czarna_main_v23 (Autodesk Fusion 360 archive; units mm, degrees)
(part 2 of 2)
sketch "Sketch1" plane through (0, 0, -98.4) normal (0, 0, 1) x axis (-1, 0, 0)
  line L1 (-270, 360.5) -> (270, 360.5)
  line L2 (-270, 342.5) -> (-270, 360.5)
  line L3 (270, 342.5) -> (-270, 342.5)
  line L4 (270, 360.5) -> (270, 342.5)
  line L5 (-249, -175.5) -> (-249, 360.5)
  line L6 (-270, 360.5) -> (-249, 360.5)
  line L7 (-270, 342.5) -> (-270, 360.5)
  line L8 (-249, 342.5) -> (-270, 342.5)
  line L9 (-249, 360.5) -> (-249, 342.5)
  line L10 (-272, 362.5) -> (-247, 362.5)
  line L11 (-272, 340.5) -> (-272, 362.5)
  line L12 (-247, 340.5) -> (-272, 340.5)
  line L13 (-247, 362.5) -> (-247, 340.5)
  line L14 (-249, 362.5) -> (-249, 360.5)
  point P4 (-270, 342.5)
  point P10 (-270, 342.5)
  point P6 (-249, 360.5)
  point P8 (-249, 360.5)
  point P16 (-249, 360.5)
  point P17 (-249, 362.5)
  horizontal L6
  vertical L7
  horizontal L8
  vertical L9
  coincident P4 P10
  coincident P6 P8
  coincident P6 P16
  coincident L10 P17
  perpendicular L10 L14
  dimension "d1" = 2
extrude "Extrude1" new body sketch "Sketch1" profile of L1 L2 L3 L5 L6 L7 L8 L9 L10 L12 L11 L14 along normal blind 18
extrude "Extrude2" add sketch "Sketch1" profile of L1 L2 L3 L5 L6 L7 L8 L10 L12 L11 L14 against normal blind 3
fillet "Fillet1" radius 5
fillet "Fillet2" radius 1
sketch "Sketch2" plane through (0, 0, -80.4) normal (0, 0, 1) x axis (-1, 0, 0)
  line L1 (-249, 341.5) -> (-267, 341.5)
  line L2 (-249, 361.5) -> (-249, 341.5)
  line L3 (-267, 361.5) -> (-249, 361.5)
  line L4 (-267, 341.5) -> (-267, 361.5)
  line L5 (-267, 351.5) -> (-249, 351.5)
  line L6 (-258, 361.5) -> (-258, 341.5)
  circle C1 centre (-258, 351.5) radius 2.5
  point P6 (-249, 351.5)
  point P7 (-267, 351.5)
  point P8 (-258, 341.5)
  point P9 (-258, 361.5)
  point P10 (-258, 351.5)
  midpoint L2 P6
  midpoint L4 P7
  midpoint L1 P8
  midpoint L3 P9
  midpoint L6 P10
  dimension "d10" diameter C1 = 5
extrude "Extrude3" cut sketch "Sketch2" profile of C1 against normal blind 18
chamfer "Chamfer1" distance 3
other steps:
derived_base_feature "Derived Base Feature1" bodies "Body1"
derived_base_feature "Derived Base Feature2" bodies "Body1 (1)"
named bodies: "Body1", "Body1 (1)"

design "front_zetki"
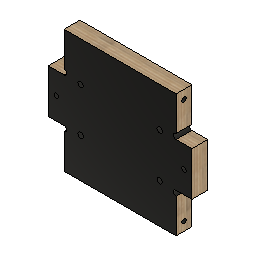
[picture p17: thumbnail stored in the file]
derived_context "$ 6e871250-6ba1-47b6-a885-2dd81215d881㸩忾盧繧$ a4974d71-8db2-4fde-91a5-83f0541c0199́   Ā䢀켓훟␀ 䔀㌰㠷䔴ⵄ䔵㤱㐭ㅅⴴ㥂㉆㌭あ〷㜱㄰䌸D  czarnula_main v53     Ā¶          뼁    Ā Āǹ   ᜁ齭冀梗æ$ ㍄㌹〷㠲䌭〲ⵃ"
sketch "Sketch1" plane through (-78.7594, 79.012, 28.9318) normal (1, 0, 0) x axis (0, 1, 0)
  line L1 (-158.024, -57.8636) -> (-258.024, -57.8636)
  line L2 (-158.024, 82.1364) -> (-158.024, -57.8636)
  line L3 (-258.024, 82.1364) -> (-158.024, 82.1364)
  line L4 (-258.024, -57.8636) -> (-258.024, 82.1364)
  line L5 (-240.024, 82.1364) -> (-258.024, 82.1364)
  line L6 (-240.024, -57.8636) -> (-240.024, 82.1364)
  line L7 (-258.024, -57.8636) -> (-240.024, -57.8636)
  line L8 (-258.024, 82.1364) -> (-258.024, -57.8636)
  circle C1 centre (-168.024, 42.1364) radius 2.5
  circle C2 centre (-200.024, -17.8636) radius 2.5
  circle C3 centre (-200.024, 42.1364) radius 2.5
  circle C4 centre (-168.024, -17.8636) radius 2.5
  circle C5 centre (-249.024, 72.1364) radius 2.5
  circle C6 centre (-249.024, -47.8636) radius 2.5
  circle C7 centre (-249.024, 12.1364) radius 2.5
  point P12 (-258.024, 82.1364)
  point P13 (-258.024, 82.1364)
  point P14 (-240.024, 82.1364)
  point P16 (-258.024, -57.8636)
  horizontal L5
  vertical L6
  horizontal L7
  vertical L8
  coincident P12 P13
  dimension "d1" distance P13 P14 = 18
  dimension "d2" distance P13 P16 = 140
extrude "Extrude1" new body sketch "Sketch1" profile of C5 C6 C7 L1 L3 L4 L5 L6 L7 L8 along normal blind 127.5
sketch "Sketch2" plane through (0, -179.012, 0) normal (0, -1, 0) x axis (1, 0, 0)
  line L1 (-78.7594, -28.9318) -> (-78.7594, 111.0682)
  line L2 (48.7406, -28.9318) -> (-78.7594, -28.9318)
  line L3 (48.7406, 111.0682) -> (48.7406, -28.9318)
  line L4 (-78.7594, 111.0682) -> (48.7406, 111.0682)
  line L5 (-15.0094, -28.9318) -> (-15.0094, 111.0682)
  line L6 (48.7406, 41.0682) -> (-78.7594, 41.0682)
  circle C1 centre (-60.0094, 66.0682) radius 3
  circle C2 centre (29.9906, 66.0682) radius 3
  circle C3 centre (-60.0094, 16.0682) radius 3
  circle C4 centre (29.9906, 16.0682) radius 3
  point P6 (-15.0094, 111.0682)
  point P7 (-15.0094, -28.9318)
  point P8 (-78.7594, 41.0682)
  point P9 (48.7406, 41.0682)
  point P10 (-60.0094, 66.0682)
  midpoint L4 P6
  midpoint L2 P7
  midpoint L1 P8
  midpoint L3 P9
  symmetric L5 C1 C2
  symmetric L6 C1 C3
  symmetric L6 C2 C4
  dimension "d5" diameter C1 = 6
  dimension "d6" distance L5 P10 = 45
  dimension "d7" distance L6 P10 = 25
extrude "Extrude2" cut sketch "Sketch2" profile of C1 C2 C3 C4 against normal blind 25
sketch "Szkic3" plane through (48.7406, 0, 0) normal (1, 0, 0) x axis (0, 1, 0)
  line L1 (-161.012, -28.9318) -> (-179.012, -28.9318)
  line L2 (-161.012, 111.0682) -> (-161.012, -28.9318)
  line L3 (-179.012, 111.0682) -> (-161.012, 111.0682)
  line L4 (-179.012, -28.9318) -> (-179.012, 111.0682)
  line L5 (-161.012, 16.0682) -> (-179.012, 16.0682)
  line L6 (-161.012, 66.0682) -> (-161.012, 16.0682)
  line L7 (-179.012, 66.0682) -> (-161.012, 66.0682)
  line L8 (-179.012, 16.0682) -> (-179.012, 66.0682)
  line L9 (-161.012, 66.0682) -> (-179.012, 16.0682)
  line L10 (-179.012, 66.0682) -> (-161.012, 16.0682)
  circle C1 centre (-170.012, 101.0682) radius 2.5
  circle C2 centre (-170.012, 41.0682) radius 2.5
  circle C3 centre (-170.012, -18.9318) radius 2.5
  point P13 (-170.012, 41.0682)
  point P3 (-170.012, 41.0682)
  point P11 (-161.012, 66.0682)
  point P12 (-179.012, 66.0682)
  point P10 (-161.012, 16.0682)
  horizontal L5
  perpendicular L5 L6
  parallel L5 L7
  parallel L6 L8
  coincident L9 P13
  coincident L10 P13
  coincident P3 P13
  dimension "d10" distance P11 P12 = 18
  dimension "d11" distance P10 P11 = 50
extrude "Wyciągnięcie proste3" add sketch "Szkic3" profile of C2 L2 L4 L5 L6 L7 L8 along normal blind 18
work_plane "Płaszczyzna konstrukcyjna"
mirror "Odbij1" mirrorStitchTolerance 0.1
sketch "Szkic4" plane through (0, -179.012, 0) normal (0, -1, 0) x axis (1, 0, 0)
  line L1 (-78.7594, -28.9318) -> (-78.7594, 16.0682)
  line L2 (48.7406, -28.9318) -> (-78.7594, -28.9318)
  line L3 (48.7406, 16.0682) -> (48.7406, -28.9318)
  line L4 (66.7406, 16.0682) -> (48.7406, 16.0682)
  line L5 (66.7406, 66.0682) -> (66.7406, 16.0682)
  line L6 (48.7406, 66.0682) -> (66.7406, 66.0682)
  line L7 (48.7406, 111.0682) -> (48.7406, 66.0682)
  line L8 (-78.7594, 111.0682) -> (48.7406, 111.0682)
  line L9 (-78.7594, 66.0682) -> (-78.7594, 111.0682)
  line L10 (-96.7594, 66.0682) -> (-78.7594, 66.0682)
  line L11 (-96.7594, 16.0682) -> (-96.7594, 66.0682)
  line L12 (-78.7594, 16.0682) -> (-96.7594, 16.0682)
  circle C1 centre (29.9906, 66.0682) radius 3
  circle C2 centre (29.9906, 16.0682) radius 3
  circle C3 centre (-60.0094, 66.0682) radius 3
  circle C4 centre (-60.0094, 16.0682) radius 3
  circle C5 centre (48.7406, 69.0682) radius 3
  circle C6 centre (48.7406, 13.0682) radius 3
  circle C7 centre (57.7406, 41.0682) radius 2.5
  point P18 (48.7406, 69.0682)
  point P19 (48.7406, 13.0682)
  point P20 (57.7406, 41.0682)
  coincident L7 P18
  coincident L3 P19
  dimension "d16" diameter C5 = 6
  dimension "d17" diameter C6 = 6
  dimension "d18" distance L4 P19 = 3
  dimension "d19" distance L6 P18 = 3
  dimension "d24" diameter C7 = 5
  dimension "d25" distance L4 P20 = 25
  dimension "d26" distance L5 P20 = 9
extrude "Wyciągnięcie proste4" cut sketch "Szkic4" profile of L3 L7 C5 C6 C7 against normal blind 20
mirror "Odbij2" mirrorStitchTolerance 0.1
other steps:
derived_base_feature "Derived Base Feature" bodies "Body1"
named bodies: "Body1"

design "karetka_dol"
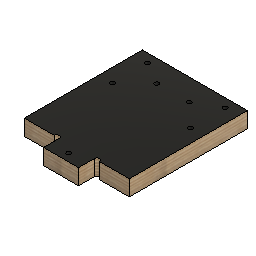
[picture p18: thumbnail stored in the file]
derived_context "$ 849fbd61-1d81-4a9c-a9ca-583caa0cf6c6챱窴Ც똯$ a4974d71-8db2-4fde-91a5-83f0541c0199́   Ā压롻䈮␀ 䔀㌰㠷䔴ⵄ䔵㤱㐭ㅅⴴ㥂㉆㌭あ〷㜱㄰䌸D  czarnula_main v45     Ā¶          뼁    Ā ĀŦ   먁䡹䫷>$ ㍄㌹〷㠲䌭〲ⵃ"
derived_context "Kontekst pochodny"
sketch "Sketch1" plane through (14, -5, -1) normal (0, -1, 0) x axis (1, 0, 0)
  line L1 (13.6, 5.7) -> (13.6, 4.3)
  line L2 (31, -23) -> (-89, -23)
  line L3 (31, 157) -> (31, -23)
  line L4 (-89, 157) -> (31, 157)
  line L5 (-89, -23) -> (-89, 157)
  line L6 (31, -23) -> (-89, -23)
  line L7 (31, -5) -> (31, -23)
  line L8 (-89, -5) -> (31, -5)
  line L9 (-89, -23) -> (-89, -5)
  arc A1 centre (16, 5) radius 2.5 clockwise from (13.6, 5.7) to (13.6, 4.3)
  circle C1 centre (16, 95) radius 2.5
  circle C2 centre (16, 127) radius 2.5
  circle C3 centre (16, 37) radius 2.5
  circle C4 centre (-74, 81) radius 2.5
  circle C5 centre (-44, 5) radius 2.5
  circle C6 centre (-44, 95) radius 2.5
  circle C7 centre (-44, 127) radius 2.5
  circle C8 centre (-44, 37) radius 2.5
  circle C9 centre (-74, 51) radius 2.5
  point P14 (-89, -23)
  point P18 (-89, -23)
  point P19 (31, -23)
  point P21 (-89, -5)
  horizontal L6
  vertical L7
  horizontal L8
  vertical L9
  coincident P14 P18
  dimension "d1" distance P18 P19 = 120
  dimension "d2" distance P18 P21 = 18
extrude "Extrude1" new body sketch "Sketch1" profile of L2 L3 L5 L6 L7 L8 L9 along normal blind 130
sketch "Sketch2" plane through (0, -135, 0) normal (0, -1, 0) x axis (1, 0, 0)
  line L1 (-75, -24) -> (-75, -6)
  line L2 (45, -24) -> (-75, -24)
  line L3 (45, -6) -> (45, -24)
  line L4 (-75, -6) -> (45, -6)
  line L5 (45, -15) -> (-75, -15)
  line L6 (-15, -24) -> (-15, -6)
  line L7 (5, -6) -> (-35, -6)
  line L8 (5, -24) -> (5, -6)
  line L9 (-35, -24) -> (5, -24)
  line L10 (-35, -6) -> (-35, -24)
  line L11 (5, -24) -> (-35, -6)
  line L12 (-35, -24) -> (5, -6)
  point P6 (-75, -15)
  point P7 (45, -15)
  point P8 (-15, -6)
  point P9 (-15, -24)
  point P14 (-15, -15)
  point P12 (5, -24)
  point P13 (-35, -24)
  point P11 (5, -6)
  midpoint L1 P6
  midpoint L3 P7
  midpoint L4 P8
  midpoint L2 P9
  horizontal L7
  perpendicular L7 L8
  parallel L7 L9
  parallel L8 L10
  coincident L11 P14
  coincident L12 P14
  midpoint L6 P14
  dimension "d5" distance P12 P13 = 40
  dimension "d6" distance P11 P12 = 18
extrude "Extrude2" add sketch "Sketch2" profile of L2 L4 L7 L8 L9 L10 along normal blind 18
sketch "Sketch3" plane through (0, 0, -6) normal (0, 0, 1) x axis (-1, 0, 0)
  line L1 (75, 5) -> (-45, 5)
  line L2 (75, 135) -> (75, 5)
  line L3 (35, 135) -> (75, 135)
  line L4 (35, 153) -> (35, 135)
  line L5 (-5, 153) -> (35, 153)
  line L6 (-5, 135) -> (-5, 153)
  line L7 (-45, 135) -> (-5, 135)
  line L8 (-45, 5) -> (-45, 135)
  circle C1 centre (38, 135) radius 3
  circle C2 centre (-8, 135) radius 3
  circle C3 centre (15, 144) radius 2.5
  point P10 (38, 135)
  point P11 (-8, 135)
  point P12 (15, 144)
  coincident L3 P10
  coincident L7 P11
  dimension "d9" diameter C1 = 6
  dimension "d10" diameter C2 = 6
  dimension "d11" distance L4 P10 = 3
  dimension "d12" distance L6 P11 = 3
  dimension "d13" diameter C3 = 5
  dimension "d14" distance L6 P12 = 20
  dimension "d15" distance L5 P12 = 9
extrude "Extrude3" cut sketch "Sketch3" profile of L3 L7 C1 C2 C3 against normal blind 21
sketch "Sketch4" plane through (0, 0, -6) normal (0, 0, 1) x axis (-1, 0, 0)
  line L1 (-45, 135) -> (-11, 135)
  line L2 (-45, 5) -> (-45, 135)
  line L3 (75, 5) -> (-45, 5)
  line L4 (75, 135) -> (75, 5)
  line L5 (41, 135) -> (75, 135)
  line L6 (35, 153) -> (35, 135)
  line L7 (-5, 153) -> (35, 153)
  line L8 (-5, 135) -> (-5, 153)
  line L9 (15, 153) -> (15, 5)
  circle C1 centre (15, 144) radius 2.5
  arc A1 centre (-8, 135) radius 3 clockwise from (-5, 135) to (-11, 135)
  arc A2 centre (38, 135) radius 3 clockwise from (41, 135) to (35, 135)
  circle C2 centre (59.5, 10) radius 2.5
  circle C3 centre (59.5, 50) radius 2.5
  circle C4 centre (-29.5, 10) radius 2.5
  circle C5 centre (-29.5, 50) radius 2.5
  point P15 (15, 5)
  point P16 (15, 153)
  point P17 (59.5, 10)
  point P18 (59.5, 50)
  midpoint L3 P15
  midpoint L7 P16
  vertical P17 P18
  symmetric L9 C2 C4
  symmetric L9 C3 C5
  dimension "d18" diameter C2 = 5
  dimension "d19" diameter C3 = 5
  dimension "d20" distance L4 P17 = 15.5
  dimension "d21" distance P17 P18 = 40
  dimension "d22" distance L7 P18 = 103
extrude "Extrude4" cut sketch "Sketch4" profile of C2 C3 C4 C5 against normal blind 20
extrude "Extrude5" add of existing geometry blind 5
sketch "Szkic" plane through (0, 0, -6) normal (0, 0, 1) x axis (-1, 0, 0)
  line L1 (-45, 135) -> (-11, 135)
  line L2 (-45, 0) -> (-45, 135)
  line L3 (75, 0) -> (-45, 0)
  line L4 (75, 135) -> (75, 0)
  line L5 (41, 135) -> (75, 135)
  line L6 (35, 153) -> (35, 135)
  line L7 (-5, 153) -> (35, 153)
  line L8 (-5, 135) -> (-5, 153)
  line L9 (4.4324, 11.6836) -> (-6.9189, 20.6918)
  line L10 (36.9189, 20.6918) -> (25.5676, 11.6836)
  line L11 (25.5676, 38.3164) -> (36.9189, 29.3083)
  line L12 (-6.9189, 29.3083) -> (4.4324, 38.3164)
  circle C1 centre (-29.5, 10) radius 2.5
  circle C2 centre (-29.5, 50) radius 2.5
  circle C3 centre (59.5, 10) radius 2.5
  circle C4 centre (59.5, 50) radius 2.5
  circle C5 centre (15, 144) radius 2.5
  arc A1 centre (-8, 135) radius 3 clockwise from (-5, 135) to (-11, 135)
  arc A2 centre (38, 135) radius 3 clockwise from (41, 135) to (35, 135)
  arc A3 centre (15, 25) radius 17 clockwise from (25.5676, 11.6836) to (4.4324, 11.6836)
  arc A4 centre (33.5, 25) radius 5.5 clockwise from (36.9189, 29.3083) to (36.9189, 20.6918)
  arc A5 centre (15, 25) radius 17 clockwise from (4.4324, 38.3164) to (25.5676, 38.3164)
  arc A6 centre (-3.5, 25) radius 5.5 clockwise from (-6.9189, 20.6918) to (-6.9189, 29.3083)
  arc A7 centre (33.5, 25) radius 4 clockwise from (30.9114, 21.9505) to (30.9114, 28.0495)
  arc A8 centre (15, 25) radius 16.201 clockwise from (30.9114, 21.9505) to (-0.9114, 21.9505)
  arc A9 centre (-3.5, 25) radius 4 clockwise from (-0.9114, 28.0495) to (-0.9114, 21.9505)
  arc A10 centre (15, 25) radius 16.201 clockwise from (-0.9114, 28.0495) to (30.9114, 28.0495)
  circle C6 centre (33.5, 25) radius 2.4
  circle C7 centre (-3.5, 25) radius 2.4
extrude "Wyciągnięcie proste" cut sketch "Szkic" profile of L7 C6 C7 against normal blind 18
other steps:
derived_base_feature "Derived Base Feature" bodies "Body1"
derived_base_feature "Pochodny element bazowy"
named bodies: "Body1"

design "Nakretka_TR8x8"
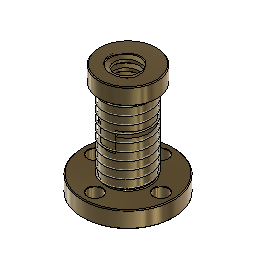
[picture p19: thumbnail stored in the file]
canvas "Canvas1"
sketch "Sketch1" plane through (0, 0, 0) normal (0, 0, 1) x axis (1, 0, 0)
  circle C1 centre (0, 0) radius 11
  circle C2 centre (0, 0) radius 3.25
  circle C3 centre (0, 0) radius 5.15
  circle C4 centre (0, 8) radius 1.75
  circle C5 centre (-8, 0) radius 1.75
  circle C6 centre (0, -8) radius 1.75
  circle C7 centre (8, 0) radius 1.75
  point P1 (0, 0)
  point P2 (0, 0)
  point P3 (0, 0)
  point P4 (0, 0)
  point P5 (0, 8)
  coincident P1 P2
  coincident P1 P3
  concentric C1 C3
  vertical P4 P5
  dimension "d1_1" diameter C1 = 22
  dimension "d2_1" diameter C2 = 6.5
  dimension "d3_1" diameter C3 = 10.3
  dimension "d4_2" diameter C4 = 3.5
  dimension "d5_2" distance P4 P5 = 8
  dimension "d7_2" C-Pattern1-Angle = 360
extrude "Extrude1" new body sketch "Sketch1" profile of C2 C3 along normal blind 15 named "d8_1"
extrude "Extrude2" add sketch "Sketch1" profile of C1 C3 C4 C5 C6 C7 along normal blind 4 named "d10_2"
sketch "Sketch2" plane through (0, 0, 15) normal (0, 0, 1) x axis (-1, 0, 0)
  line L1 (1.8, 8.9456) -> (-1.8, 8.9456)
  line L2 (1.8, -8.9456) -> (1.8, 8.9456)
  line L3 (-1.8, -8.9456) -> (1.8, -8.9456)
  line L4 (-1.8, 8.9456) -> (-1.8, -8.9456)
  line L5 (1.8, -8.9456) -> (-1.8, 8.9456)
  line L6 (-1.8, -8.9456) -> (1.8, 8.9456)
  circle C1 centre (0, 0) radius 3.25
  circle C2 centre (0, 0) radius 5.15
  point P7 (0, 0)
  point P1 (0, 0)
  point P5 (1.8, -8.9456)
  point P6 (-1.8, -8.9456)
  horizontal L1
  perpendicular L1 L2
  parallel L1 L3
  parallel L2 L4
  coincident L5 P7
  coincident L6 P7
  coincident P1 P7
  dimension "d12_2" distance P5 P6 = 3.6
extrude "Extrude3" add sketch "Sketch2" profile of C1 C2 L2 L4 against normal blind 3.6 named "d13_2"
extrude "Extrude4" cut sketch "Sketch2" profile of C1 C2 L2 L4 against normal blind 3.6 named "d15_1"
component_from_bodies "Body->Comp1"
thread "Thread1"
sketch "Sketch3" plane through (0, 0, 15) normal (0, 0, 1) x axis (-1, 0, 0)
  line L1 (-1.8, -2.5162) -> (-1.8, -4.8252)
  line L2 (-1.8, 4.8252) -> (-1.8, 2.5162)
  arc A1 centre (0, 0) radius 3.0937 clockwise from (-1.8, -2.5162) to (-1.8, 2.5162)
  arc A2 centre (0, 0) radius 5.15 clockwise from (-1.8, -4.8252) to (-1.8, 4.8252)
work_plane "WorkPlane1" sketch "Sketch3" AlongDistance 15 named "d17_2"
sketch "Sketch4" plane through (3.475, 0, 30) normal (0, 0, 1) x axis (1, 0, 0)
  line L1 (-1.725, -16) -> (-5.225, -16)
  line L2 (-1.725, 16) -> (-1.725, -16)
  line L3 (-5.225, 16) -> (-1.725, 16)
  line L4 (-5.225, -16) -> (-5.225, 16)
  line L5 (-1.725, 16) -> (-5.225, -16)
  line L6 (-5.225, 16) -> (-1.725, -16)
  circle C1 centre (-3.475, 0) radius 7
  circle C2 centre (-3.475, 0) radius 5.15
  circle C3 centre (-3.475, 0) radius 3.25
  point P2 (-3.475, 0)
  point P3 (-3.475, 0)
  point P10 (-3.475, 0)
  point P8 (-1.725, 16)
  point P9 (-5.225, 16)
  coincident P2 P3
  concentric C1 C2
  concentric C1 C3
  horizontal L1
  perpendicular L1 L2
  parallel L1 L3
  parallel L2 L4
  coincident L5 P10
  coincident L6 P10
  coincident P3 P10
  dimension "d18_2" diameter C1 = 14
  dimension "d19_2" diameter C2 = 10.3
  dimension "d20_2" diameter C3 = 6.5
  dimension "d25" distance P8 P9 = 3.5
extrude "Extrude5" new body sketch "Sketch4" profile of C1 C2 against normal blind 4 named "d21_2"
extrude "Extrude6" new body sketch "Sketch4" profile of C2 C3 against normal blind 10.7 named "d23_2"
extrude "Extrude7" add sketch "Sketch4" profile of C2 C3 L2 L4 against normal blind 15
thread "Thread1"
move "Move1"
fillet "Fillet1" radius 0.2 named "d29_1"
fillet "Fillet2" radius 0.2 named "d33_2"
component_from_bodies "Body->Comp2"
coil_primitive "CoilPrimitive1" Diameter 11 named "d36_2" SectionSize 0.3 named "d37_2" TaperAngle 0 named "d38_1" Revolutions 10 named "d39_1" Height 19 named "d40_1"
fillet "Fillet3" radius 0.1 named "d42_1"
position "Position1"
position "Position5"
as_built_joint "As-built1"
as_built_joint "As-built2"
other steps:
base_feature "Base Feature1"
base_feature "Base Feature1"
fillet "Fillet1" radius 0.2 named "d31_1"
fillet "Fillet2" radius 0.2 named "d35_2"
create_component "CreateComponent1"
remove_body "RemoveBody1"
create_component "CreateComponent2"
remove_body "RemoveBody2"
create_component "CreateComponent3"

design "mocowanie_silnika"
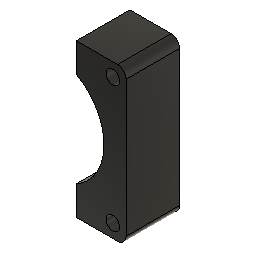
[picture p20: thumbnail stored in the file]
derived_context "$ 3c1ed40b-f86d-498b-aeb9-da3c8378fe9c䋽ꦡ䅱䐟$ a4974d71-8db2-4fde-91a5-83f0541c0199́   Ā땰ⲉ짦竑␀ 䔀㌰㠷䔴ⵄ䔵㤱㐭ㅅⴴ㥂㉆㌭あ〷㜱㄰䌸D  czarnula_main v9     Ā¶          뼁    Ā Ā╆   瀁覵퇉z$ ㍄㌹〷㠲䌭〲ⵃ䔴"
sketch "Sketch1" plane through (0, 175.5, 0) normal (0, 1, 0) x axis (-1, 0, 0)
  line L1 (270, -223.4) -> (-270, -223.4)
  line L2 (270, -98.4) -> (270, -223.4)
  line L3 (-270, -98.4) -> (270, -98.4)
  line L4 (-270, -223.4) -> (-270, -98.4)
  line L5 (-208.425, -184.1531) -> (-208.425, -203.8)
  line L6 (-208.425, -153) -> (-208.425, -172.6469)
  line L7 (-262.4, -149.825) -> (-211.6, -149.825)
  line L8 (-265.575, -203.8) -> (-265.575, -153)
  line L9 (-211.6, -206.975) -> (-262.4, -206.975)
  line L10 (-207.7138, -184.1531) -> (-208.425, -184.1531)
  line L11 (-208.425, -172.6469) -> (-207.7138, -172.6469)
  line L12 (-207.409, -183.3911) -> (-207.409, -183.8483)
  line L13 (-207.409, -173.4089) -> (-207.409, -183.3911)
  line L14 (-207.409, -172.9517) -> (-207.409, -173.4089)
  line L15 (-237, -206.975) -> (-237, -149.825)
  line L16 (-247, -206.975) -> (-247, -149.825)
  circle C1 centre (-237, -159.9) radius 2.4
  circle C2 centre (-237, -196.9) radius 2.4
  circle C3 centre (-260.622, -154.778) radius 2.54
  circle C4 centre (-213.378, -154.778) radius 2.54
  circle C5 centre (-260.622, -202.022) radius 2.54
  circle C6 centre (-213.378, -202.022) radius 2.54
  circle C7 centre (-237, -178.4) radius 15
  circle C8 centre (-213.378, -154.778) radius 2.54
  circle C9 centre (-213.378, -202.022) radius 2.54
  circle C10 centre (-260.622, -202.022) radius 2.54
  circle C11 centre (-260.622, -154.778) radius 2.54
  circle C12 centre (-237, -178.4) radius 3.175
  arc A1 centre (-211.6, -203.8) radius 3.175 clockwise from (-208.425, -203.8) to (-211.6, -206.975)
  arc A2 centre (-211.6, -153) radius 3.175 clockwise from (-211.6, -149.825) to (-208.425, -153)
  arc A3 centre (-262.4, -153) radius 3.175 clockwise from (-265.575, -153) to (-262.4, -149.825)
  arc A4 centre (-262.4, -203.8) radius 3.175 clockwise from (-262.4, -206.975) to (-265.575, -203.8)
  arc A5 centre (-207.7138, -172.9517) radius 0.3048 clockwise from (-207.7138, -172.6469) to (-207.409, -172.9517)
  arc A6 centre (-207.7138, -183.8483) radius 0.3048 clockwise from (-207.409, -183.8483) to (-207.7138, -184.1531)
  circle C13 centre (-237, -178.4) radius 20.32
  point P40 (-237, -149.825)
  point P41 (-237, -206.975)
  midpoint L7 P40
  midpoint L9 P41
  dimension "d1" = 10
extrude "Extrude2" new body sketch "Sketch1" profile of C3 C5 C10 C11 L7 A3 L8 A4 L9 L16 C13 along normal blind 20
extrude "Extrude1" new body sketch "Sketch1" profile of C3 C5 C7 C10 C11 L7 A3 L8 A4 L9 L16 along normal blind 20
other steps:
derived_base_feature "Derived Base Feature1" bodies "Body1"
derived_base_feature "Derived Base Feature2" bodies "Body1 (1)"
named bodies: "Body1", "Body1 (1)"

design "sprzeglo_6,35x8mm"
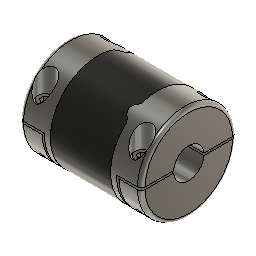
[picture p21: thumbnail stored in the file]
base_feature "Base Feature1"
base_feature "Base Feature1"
base_feature "Base Feature1"
as_built_joint "As-built1"
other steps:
create_component "CreateComponent1"
create_component "CreateComponent2"
create_component "CreateComponent3"

design "baza_tyl_front"
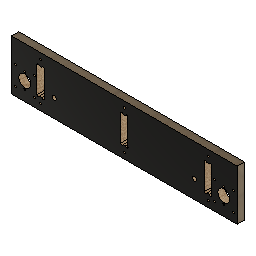
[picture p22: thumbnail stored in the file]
derived_context "$ d8fb076e-8401-47e9-bcfb-4a3807aecd66⧜ꖑ㛑$ a4974d71-8db2-4fde-91a5-83f0541c0199́   Ā찴玐⭸␀ 䔀㌰㠷䔴ⵄ䔵㤱㐭ㅅⴴ㥂㉆㌭あ〷㜱㄰䌸D  czarnula_main v16     Ā¶          뼁    Ā Ā╆   㐁擌郳硳+$ ㍄㌹〷㠲䌭〲ⵃ"
sketch "Sketch1" plane through (0, 175.5, 0) normal (0, 1, 0) x axis (-1, 0, 0)
  line L1 (270, -223.4) -> (-270, -223.4)
  line L2 (-270, -98.4) -> (270, -98.4)
  line L3 (-270, -223.4) -> (-270, -98.4)
  line L4 (270, -98.4) -> (-270, -98.4)
  line L5 (-270, -223.4) -> (270, -223.4)
  line L6 (-270, -98.4) -> (-270, -223.4)
  line L7 (-207, -223.4) -> (-207, -98.4)
  line L8 (-189, -223.4) -> (-207, -223.4)
  line L9 (-189, -98.4) -> (-189, -223.4)
  line L10 (-207, -98.4) -> (-189, -98.4)
  line L11 (0, -223.4) -> (0, -98.4)
  line L12 (290, -98.4) -> (270, -98.4)
  line L13 (290, -223.4) -> (290, -98.4)
  line L14 (270, -223.4) -> (290, -223.4)
  line L15 (10, -223.4) -> (10, -98.4)
  line L16 (290, -223.4) -> (290, -98.4)
  line L17 (290, -98.4) -> (290, -223.4)
  line L18 (209, -98.4) -> (209, -223.4)
  line L19 (227, -98.4) -> (209, -98.4)
  line L20 (227, -223.4) -> (227, -98.4)
  line L21 (209, -223.4) -> (227, -223.4)
  line L22 (-189, -128.4) -> (-207, -128.4)
  line L23 (-189, -193.4) -> (-189, -128.4)
  line L24 (-207, -193.4) -> (-189, -193.4)
  line L25 (-207, -128.4) -> (-207, -193.4)
  line L26 (209, -128.4) -> (227, -128.4)
  line L27 (227, -193.4) -> (209, -193.4)
  line L28 (218, -160.9) -> (-198, -160.9)
  line L29 (19, -193.4) -> (1, -193.4)
  line L30 (19, -128.4) -> (19, -193.4)
  line L31 (1, -128.4) -> (19, -128.4)
  line L32 (1, -193.4) -> (1, -128.4)
  line L33 (19, -128.4) -> (1, -193.4)
  line L34 (1, -128.4) -> (19, -193.4)
  circle C1 centre (-237, -159.9) radius 2.4
  circle C2 centre (-237, -196.9) radius 2.4
  circle C3 centre (-260.622, -154.778) radius 2.54
  circle C4 centre (-213.378, -154.778) radius 2.54
  circle C5 centre (-260.622, -202.022) radius 2.54
  circle C6 centre (-213.378, -202.022) radius 2.54
  circle C7 centre (-237, -178.4) radius 15
  circle C8 centre (-260.622, -154.778) radius 2.5
  circle C9 centre (-213.378, -154.778) radius 2.5
  circle C10 centre (-260.622, -202.022) radius 2.5
  circle C11 centre (-213.378, -202.022) radius 2.5
  circle C12 centre (-237, -196.9) radius 2.5
  circle C13 centre (-237, -159.9) radius 2.5
  circle C14 centre (-237, -178.4) radius 15
  circle C15 centre (-198, -113.4) radius 2.5
  circle C16 centre (-198, -208.4) radius 2.5
  circle C17 centre (-198, -160.9) radius 2.5
  circle C18 centre (-164, -178.4) radius 5
  circle C19 centre (257, -159.9) radius 2.5
  circle C20 centre (233.378, -154.778) radius 2.5
  circle C21 centre (184, -178.4) radius 5
  circle C22 centre (280.622, -202.022) radius 2.54
  circle C23 centre (280.622, -202.022) radius 2.5
  circle C24 centre (233.378, -202.022) radius 2.5
  circle C25 centre (257, -178.4) radius 15
  circle C26 centre (233.378, -202.022) radius 2.54
  circle C27 centre (218, -208.4) radius 2.5
  circle C28 centre (218, -160.9) radius 2.5
  circle C29 centre (233.378, -154.778) radius 2.54
  circle C30 centre (257, -178.4) radius 15
  circle C31 centre (280.622, -154.778) radius 2.54
  circle C32 centre (257, -196.9) radius 2.4
  circle C33 centre (257, -196.9) radius 2.5
  circle C34 centre (218, -113.4) radius 2.5
  circle C35 centre (280.622, -154.778) radius 2.5
  circle C36 centre (257, -159.9) radius 2.4
  circle C37 centre (10, -208.4) radius 2.5
  circle C38 centre (10, -113.4) radius 2.5
  circle C39 centre (-237, -128.4) radius 5
  circle C40 centre (257, -128.4) radius 5
  circle C41 centre (212, -193.4) radius 3
  circle C42 centre (224, -193.4) radius 3
  circle C43 centre (212, -128.4) radius 3
  circle C44 centre (224, -128.4) radius 3
  circle C45 centre (-192, -193.4) radius 3
  circle C46 centre (-204, -193.4) radius 3
  circle C47 centre (-192, -128.4) radius 3
  circle C48 centre (-204, -128.4) radius 3
  circle C49 centre (4, -193.4) radius 3
  circle C50 centre (16, -193.4) radius 3
  circle C51 centre (16, -128.4) radius 3
  circle C52 centre (4, -128.4) radius 3
  point P10 (270, -223.4)
  point P15 (270, -223.4)
  point P12 (-270, -98.4)
  point P13 (-270, -98.4)
  point P31 (0, -98.4)
  point P32 (0, -223.4)
  point P36 (10, -98.4)
  point P37 (10, -223.4)
  point P9 (-270, -223.4)
  point P42 (290, -223.4)
  point P63 (290, -98.4)
  point P51 (290, -98.4)
  point P16 (-270, -223.4)
  point P41 (290, -223.4)
  point P25 (-207, -98.4)
  point P38 (227, -98.4)
  point P26 (-207, -223.4)
  point P58 (227, -223.4)
  point P27 (-189, -223.4)
  point P39 (209, -223.4)
  point P28 (-189, -98.4)
  point P59 (209, -98.4)
  point P66 (-189, -193.4)
  point P64 (-207, -128.4)
  point P68 (227, -128.4)
  point P65 (-189, -128.4)
  point P69 (209, -128.4)
  point P70 (209, -193.4)
  point P67 (-207, -193.4)
  point P71 (227, -193.4)
  point P30 (-198, -160.9)
  point P72 (-198, -160.9)
  point P54 (218, -160.9)
  point P73 (218, -160.9)
  point P78 (10, -160.9)
  point P79 (10, -208.4)
  point P80 (10, -113.4)
  point P83 (212, -193.4)
  point P84 (224, -193.4)
  point P91 (4, -193.4)
  point P92 (16, -193.4)
  point P24 (-198, -113.4)
  point P29 (-198, -208.4)
  point P33 (-164, -178.4)
  point P76 (19, -128.4)
  point P77 (1, -128.4)
  point P75 (19, -193.4)
  point P81 (-237, -128.4)
  horizontal L4
  horizontal L5
  vertical L6
  coincident P10 P15
  coincident P12 P13
  concentric C3 C8
  concentric C4 C9
  concentric C5 C10
  concentric C6 C11
  concentric C2 C12
  concentric C1 C13
  concentric C7 C14
  midpoint L4 P31
  midpoint L5 P32
  parallel L2 L12
  perpendicular L1 L13
  perpendicular L13 L14
  coincident L2 P36
  coincident L1 P37
  perpendicular L1 L15
  symmetric C1 L15 C36
  symmetric C2 L15 C32
  symmetric C3 L15 C31
  symmetric C4 L15 C29
  symmetric C5 L15 C22
  symmetric C6 L15 C26
  symmetric C7 L15 C25
  symmetric P9 L15 P42
  symmetric P12 L15 P63
  symmetric P13 L15 P51
  symmetric P16 L15 P41
  symmetric C8 L15 C35
  symmetric C9 L15 C20
  symmetric C10 L15 C23
  symmetric C11 L15 C24
  symmetric C12 L15 C33
  symmetric C13 L15 C19
  symmetric C14 L15 C30
  symmetric C15 L15 C34
  symmetric P25 L15 P38
  symmetric P26 L15 P58
  symmetric P27 L15 P39
  symmetric P28 L15 P59
  symmetric C16 L15 C27
  symmetric C17 L15 C28
  symmetric C18 L15 C21
  horizontal L22
  vertical L23
  horizontal L24
  vertical L25
  coincident L9 P66
  coincident L7 P64
  symmetric L15 P64 P68
  symmetric L15 P65 P69
  symmetric L15 P66 P70
  symmetric L15 P67 P71
  coincident P30 P72
  coincident P54 P73
  horizontal L29
  perpendicular L29 L30
  parallel L29 L31
  parallel L30 L32
  coincident L33 P78
  coincident L34 P78
  midpoint L28 P78
  coincident L15 P79
  coincident L15 P80
  symmetric L15 C39 C40
  coincident L27 P83
  coincident L27 P84
  symmetric L28 C41 C43
  symmetric L28 C42 C44
  symmetric L15 C41 C45
  symmetric L15 C42 C46
  symmetric L15 C43 C47
  symmetric L15 C44 C48
  coincident L29 P91
  coincident L29 P92
  symmetric L28 C49 C52
  symmetric L28 C50 C51
  dimension "d1" diameter C8 = 5
  dimension "d2" diameter C9 = 5
  dimension "d3" diameter C10 = 5
  dimension "d4" diameter C11 = 5
  dimension "d5" diameter C12 = 5
  dimension "d6" diameter C13 = 5
  dimension "d7" diameter C14 = 30
  dimension "d8" diameter C15 = 5
  dimension "d10" distance P24 L7 = 9
  dimension "d11" distance P24 P28 = 15
  dimension "d12" diameter C16 = 5
  dimension "d13" distance P26 P29 = 9
  dimension "d14" distance L5 P29 = 15
  dimension "d15" distance L9 P30 = 9
  dimension "d16" diameter C17 = 5
  dimension "d17" distance P27 P30 = 62.5
  dimension "d20" diameter C18 = 10
  dimension "d21" distance L5 P33 = 45
  dimension "d22" distance L9 P33 = 25
  dimension "d27" distance L6 L13 = 560
  dimension "d28" distance L11 L15 = 10
  dimension "d29" distance L4 L22 = 30
  dimension "d30" distance L5 L24 = 30
  dimension "d31" distance P76 P77 = 18
  dimension "d32" distance P75 P76 = 65
  dimension "d33" diameter C37 = 5
  dimension "d34" diameter C38 = 5
  dimension "d35" distance L5 P79 = 15
  dimension "d36" distance L4 P80 = 15
  dimension "d37" diameter C39 = 10
  dimension "d38" distance L4 P81 = 30
  dimension "d39" distance L6 P81 = 33
  dimension "d40" diameter C41 = 6
  dimension "d41" diameter C42 = 6
  dimension "d42" distance L18 P83 = 3
  dimension "d43" distance L20 P84 = 3
  dimension "d44" diameter C49 = 6
  dimension "d45" diameter C50 = 6
  dimension "d46" distance L32 P91 = 3
  dimension "d47" distance L30 P92 = 3
extrude "Extrude1" new body sketch "Sketch1" profile of C3 C4 C5 C6 C7 L1 L2 L3 L4 L5 L6 C12 C13 C14 C15 L7 L8 L9 L10 C16 C18 L12 L13 L14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 against normal blind 18
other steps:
derived_base_feature "Derived Base Feature1" bodies "Body1"
derived_base_feature "Derived Base Feature2" bodies "Body1 (1)"
named bodies: "Body1", "Body1 (1)"

design "SMA_16_UU"
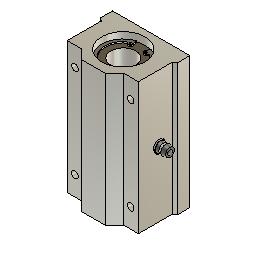
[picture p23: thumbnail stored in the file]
base_feature "Base Feature"
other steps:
create_component "CreateComponent1"
create_component "CreateComponent1"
